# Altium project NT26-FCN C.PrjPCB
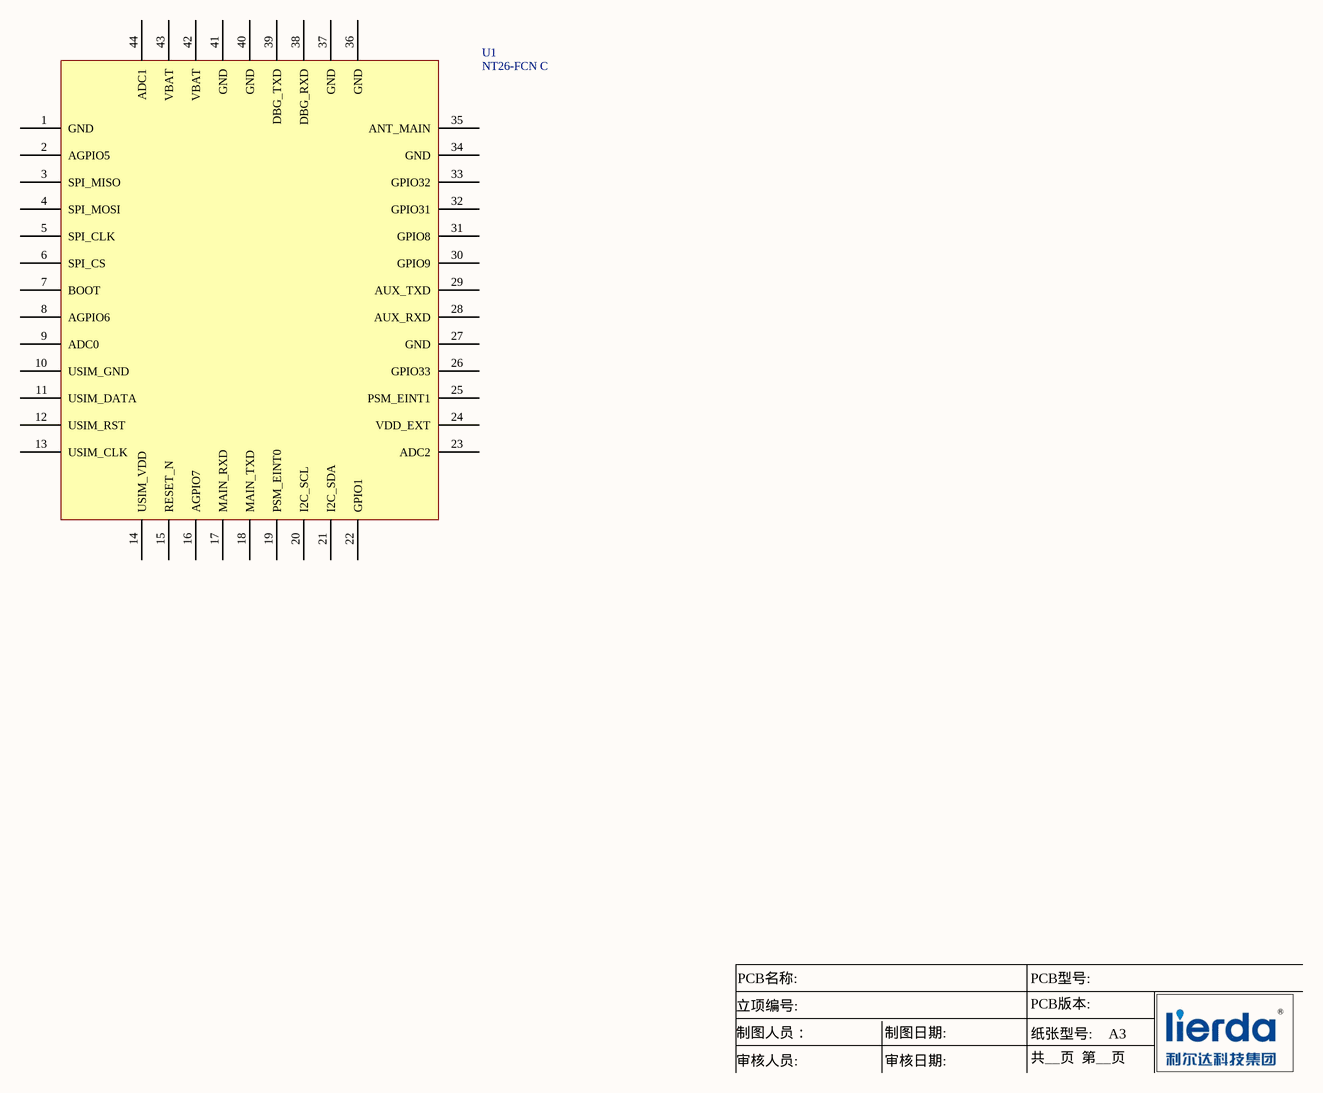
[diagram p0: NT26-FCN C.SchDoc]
立项编号: XXXXXX; 项目名称: NT26FCNC00WNA Cat1模组; 项目型号: NT26FCNC00WNA
1 sheet, 1 parts. Net scope: global (net labels, ports and power ports of the same name join across sheets).
Board file: NT26-FCN C.PcbDoc

## Sheet NT26-FCN C.SchDoc
size A3

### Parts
U1  NT26-FCN C  [NT26-FCN C]

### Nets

Not connected (* = marked no-connect by the designer): U1 1(GND) 2(AGPIO5) 3(SPI_MISO) 4(SPI_MOSI) 5(SPI_CLK) 6(SPI_CS) 7(BOOT) 8(AGPIO6) 9(ADC0) 10(USIM_GND) 11(USIM_DATA) 12(USIM_RST) 13(USIM_CLK) 14(USIM_VDD) 15(RESET_N) 16(AGPIO7) 17(MAIN_RXD) 18(MAIN_TXD) 19(PSM_EINT0) 20(I2C_SCL) 21(I2C_SDA) 22(GPIO1) 23(ADC2) 24(VDD_EXT) 25(PSM_EINT1) 26(GPIO33) 27(GND) 28(AUX_RXD) 29(AUX_TXD) 30(GPIO9) 31(GPIO8) 32(GPIO31) 33(GPIO32) 34(GND) 35(ANT_MAIN) 36(GND) 37(GND) 38(DBG_RXD) 39(DBG_TXD) 40(GND) 41(GND) 42(VBAT) 43(VBAT) 44(ADC1)

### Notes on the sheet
- PCB名称:
- PCB型号:
- 制图人员：
- 立项编号:
- 制图日期:
- PCB版本:
- 纸张型号:
- A3
- 审核人员:
- 审核日期:
- 共__页  第__页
